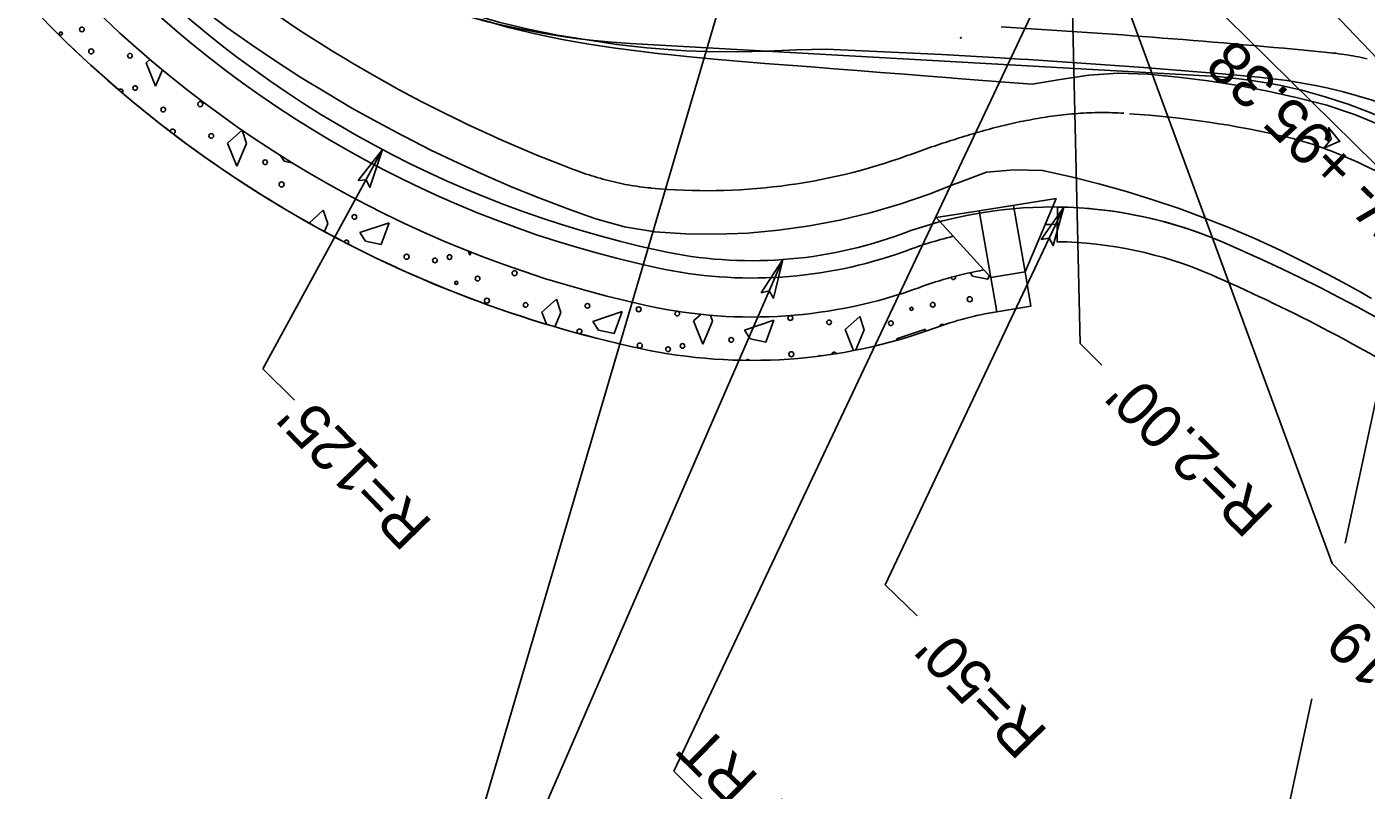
# Model space of a CAD drawing. Extents: x 1262642 to 1268358, y 767825 to 773481.
# Drawn here: x 1266640.8 to 1266795.4, y 772031 to 772119 of the extents above; entities that cross this region are included whole.
import ezdxf

# ---------------------------------------------------------------- set-up
doc = ezdxf.new("R2010")
doc.units = 0
for name, color, linetype in [('Old_Level_20', 7, 'Continuous'), ('Prop Conc 2ft 6in Curb and Gutter', 7, 'Continuous'), ('Prop Conc 4in Sidewalk', 7, 'Continuous'), ('Prop Dimension', 7, 'Continuous'), ('Prop Dimension Text', 7, 'Continuous'), ('Prop EOT', 7, 'Continuous'), ('Prop Horizontal Alignment', 7, 'Continuous'), ('Prop Lane Lines', 7, 'Continuous'), ('Prop Paved Shoulder', 7, 'Continuous'), ('Prop Shade Light', 7, 'Continuous'), ('Prop Terminator CELL', 7, 'Continuous'), ('Scratch_Level_3', 7, 'Continuous')]:
    doc.layers.add(name, color=color, linetype=linetype)

msp = doc.modelspace()

# ---------------------------------------------------------------- linework, layer by layer
at = {"layer": 'Old_Level_20'}
for p, q in [((1266750.7, 772097.82), (1266759.58, 772099.23)), ((1266759.58, 772099.23), (1266755.99, 772090.77)), ((1266745.74, 772097.04), (1266750.7, 772097.82)), ((1266750.7, 772097.81), (1266752.04, 772090.12)), ((1266755.99, 772090.77), (1266754.65, 772098.45)), ((1266752.04, 772090.12), (1266745.74, 772097.04)), ((1266752.04, 772090.12), (1266755.99, 772090.77)), ((1266752.72, 772086.18), (1266752.04, 772090.12)), ((1266755.99, 772090.77), (1266756.67, 772086.82)), ((1266756.67, 772086.82), (1266752.72, 772086.18))]:
    msp.add_line(p, q, dxfattribs=at)
at = {"layer": 'Prop Conc 2ft 6in Curb and Gutter'}
for p, q in [((1266654.56, 772114.87), (1266655.01, 772115.27)), ((1266655.64, 772112.19), (1266654.56, 772114.87)), ((1266656.45, 772114.08), (1266655.64, 772112.19)), ((1266663.94, 772105.63), (1266665.63, 772107.12)), ((1266665.63, 772107.12), (1266666.15, 772105.59)), ((1266665.02, 772102.95), (1266663.94, 772105.63)), ((1266666.15, 772105.59), (1266665.02, 772102.95)), ((1266670.07, 772104.21), (1266670.5, 772103.56)), ((1266670.5, 772103.56), (1266671.38, 772103.37)), ((1266673.36, 772096.41), (1266675.01, 772097.88)), ((1266675.01, 772097.88), (1266675.54, 772096.34)), ((1266675.54, 772096.34), (1266675.15, 772095.45)), ((1266682.61, 772096.43), (1266679.24, 772095.3)), ((1266681.69, 772093.93), (1266682.61, 772096.43)), ((1266679.24, 772095.3), (1266679.88, 772094.31)), ((1266679.88, 772094.31), (1266681.69, 772093.93)), ((1266691.91, 772092.7), (1266691.71, 772093.21)), ((1266692.07, 772093.06), (1266691.91, 772092.7)), ((1266749.66, 772090.69), (1266749.91, 772090.3)), ((1266749.91, 772090.3), (1266751.71, 772089.93)), ((1266751.71, 772089.93), (1266751.86, 772090.32)), ((1266700.22, 772086.13), (1266701.9, 772087.63)), ((1266701.9, 772087.63), (1266702.43, 772086.1)), ((1266700.78, 772084.74), (1266700.22, 772086.13)), ((1266702.43, 772086.1), (1266701.72, 772084.45)), ((1266709.5, 772086.19), (1266706.13, 772085.05)), ((1266706.13, 772085.05), (1266706.77, 772084.06)), ((1266708.58, 772083.69), (1266709.5, 772086.19)), ((1266717.72, 772085.13), (1266718.6, 772085.92)), ((1266718.8, 772082.45), (1266717.72, 772085.13)), ((1266719.93, 772085.1), (1266718.8, 772082.45)), ((1266719.69, 772085.8), (1266719.93, 772085.1)), ((1266727, 772085.19), (1266723.63, 772084.05)), ((1266726.08, 772082.69), (1266727, 772085.19)), ((1266735.23, 772084.13), (1266736.92, 772085.63)), ((1266736.92, 772085.63), (1266737.44, 772084.1)), ((1266706.77, 772084.06), (1266708.58, 772083.69)), ((1266723.63, 772084.05), (1266724.28, 772083.06)), ((1266736.2, 772081.73), (1266735.23, 772084.13)), ((1266737.44, 772084.1), (1266736.45, 772081.77)), ((1266744.51, 772084.18), (1266741.14, 772083.05)), ((1266744.41, 772083.93), (1266744.51, 772084.18)), ((1266724.28, 772083.06), (1266726.08, 772082.69)), ((1266741.14, 772083.05), (1266741.23, 772082.91))]:
    msp.add_line(p, q, dxfattribs=at)
for centre, radius in [((1266647.15, 772118.73), 0.268), ((1266644.72, 772118.26), 0.18), ((1266648.23, 772116.2), 0.285), ((1266652.7, 772115.7), 0.268), ((1266653.3, 772111.98), 0.268), ((1266656.54, 772109.49), 0.268), ((1266660.81, 772110.12), 0.292), ((1266662.08, 772106.46), 0.268), ((1266668.3, 772103.42), 0.268), ((1266670.2, 772100.87), 0.292), ((1266678.6, 772097.11), 0.268), ((1266684.62, 772092.52), 0.289), ((1266689.57, 772092.49), 0.268), ((1266687.89, 772092.1), 0.268), ((1266690.37, 772089.52), 0.18), ((1266692.81, 772090), 0.268), ((1266697.09, 772090.63), 0.292), ((1266749.61, 772087.62), 0.292), ((1266693.89, 772087.46), 0.285), ((1266698.35, 772086.96), 0.268), ((1266705.49, 772086.86), 0.268), ((1266711.4, 772086.46), 0.285), ((1266742.89, 772086.52), 0.18), ((1266745.33, 772086.99), 0.268), ((1266715.86, 772085.96), 0.268), ((1266728.9, 772085.46), 0.285), ((1266733.37, 772084.96), 0.268), ((1266740.51, 772084.86), 0.268), ((1266711.52, 772082.28), 0.289), ((1266714.79, 772081.85), 0.268), ((1266716.46, 772082.24), 0.268), ((1266722.08, 772082.93), 0.268), ((1266729.02, 772081.28), 0.289)]:
    msp.add_circle(centre, radius, dxfattribs=at)
for centre, radius, start, end in [((1266740.24, 772215.4), 127, 223.2333, 257.87), ((1266740.24, 772215.4), 131.5, 223.2333, 257.87), ((1266740.24, 772215.4), 136.5, 223.2592, 257.87), ((1266651.62, 772111.59), 0.268, 318.3312, 138.9797), ((1266657.62, 772106.95), 0.285, 170.4753, 172.1798), ((1266657.62, 772106.95), 0.285, 293.7842, 170.4753), ((1266671.46, 772097.21), 0.268, 52.9324, 66.0296), ((1266759.1, 772048.26), 48, 89.4703, 90.9427), ((1266677.68, 772094.17), 0.268, 47.9203, 169.4069), ((1266677.68, 772094.17), 0.268, 315.4588, 47.9203), ((1266759.1, 772048.26), 48, 103.7447, 110.943), ((1266724.48, 772142.07), 52, 257.87, 289.6213), ((1266747.71, 772090.17), 0.268, 185.1215, 35.1369), ((1266724.48, 772142.07), 56.5, 257.87, 290.0389), ((1266723, 772085.86), 0.268, 238.6336, 297.1958), ((1266758.89, 772048.15), 38.53, 99.2167, 110.256), ((1266704.57, 772083.93), 0.268, 14.8235, 233.9093), ((1266704.57, 772083.93), 0.268, 275.3587, 14.8235), ((1266724.48, 772142.07), 61.5, 257.87, 290.0389), ((1266746.41, 772084.45), 0.285, 45.4739, 172.2714), ((1266723.98, 772080.38), 0.292, 44.3986, 131.4308), ((1266732.29, 772080.85), 0.268, 69.0863, 122.8499), ((1266733.97, 772081.24), 0.268, 30.3392, 169.6491)]:
    msp.add_arc(centre, radius, start, end, dxfattribs=at)
at = {"layer": 'Prop Conc 4in Sidewalk'}
for centre, radius, start, end in [((1266740.24, 772215.4), 131.5, 223.2333, 257.87), ((1266740.24, 772215.4), 136.5, 223.2333, 257.87), ((1266758.89, 772048.15), 43.53, 100.1322, 110.256), ((1266724.48, 772142.07), 56.5, 257.87, 290.0389), ((1266758.89, 772048.15), 38.53, 99.2167, 110.256), ((1266724.48, 772142.07), 61.5, 257.87, 290.0389)]:
    msp.add_arc(centre, radius, start, end, dxfattribs=at)
at = {"layer": 'Prop Dimension'}
for p, q in [((1266722.9, 772128.88), (1266688.04, 772010.59)), ((1266761.3, 772127.13), (1266762.34, 772082.5)), ((1266759.33, 772125.95), (1266715.46, 772033.19)), ((1266681.85, 772104.87), (1266668.05, 772079.59)), ((1266760.45, 772098.24), (1266739.86, 772054.7)), ((1266728.03, 772092.2), (1266697.28, 772021.6))]:
    msp.add_line(p, q, dxfattribs=at)
at = {"layer": 'Prop Dimension Text'}
for p, q in [((1266820.02, 772079.89), (1266772.47, 772126.74)), ((1266791.44, 772057.15), (1266767.03, 772123.52)), ((1266762.33, 772082.5), (1266764.86, 772080.01)), ((1266668.05, 772079.59), (1266671.7, 772075.98)), ((1266832.76, 772014.09), (1266791.44, 772057.15)), ((1266739.86, 772054.7), (1266743.52, 772051.1)), ((1266715.46, 772033.19), (1266758.9, 771990.39))]:
    msp.add_line(p, q, dxfattribs=at)
for points in [[(1266792.94, 772059.49), (1266798.9, 772087.24)], [(1266785.55, 772025.08), (1266789.08, 772041.54)]]:
    msp.add_lwpolyline(points, dxfattribs=at)
at = {"layer": 'Prop EOT'}
for centre, radius, start, end in [((1266740.24, 772215.4), 125, 223.2333, 257.87), ((1266759.1, 772048.26), 50, 66.6575, 110.256), ((1266724.48, 772142.07), 50, 257.87, 290.256), ((1266699.67, 771910.54), 200, 44.1752, 66.6575)]:
    msp.add_arc(centre, radius, start, end, dxfattribs=at)
at = {"layer": 'Prop Horizontal Alignment'}
msp.add_arc((1275047.31, 780021.23), 11400, 222.993587, 225.404319, dxfattribs=at)
at = {"layer": 'Prop Lane Lines'}
msp.add_line((1266710.41, 772117.12), (1266776.78, 772113.4), dxfattribs=at)
for centre, radius, start, end in [((1275047.31, 780021.23), 11427, 222.993587, 225.36373), ((1266715.28, 772203.99), 87, 223.2333, 266.7861), ((1266773.42, 772053.49), 60, 43.9174, 86.7861)]:
    msp.add_arc(centre, radius, start, end, dxfattribs=at)
at = {"layer": 'Prop Paved Shoulder'}
for centre, radius, start, end in [((1266759.1, 772048.26), 46, 66.6575, 89.2851), ((1266699.67, 771910.54), 196, 58.2697, 66.6575)]:
    msp.add_arc(centre, radius, start, end, dxfattribs=at)
at = {"layer": 'Prop Shade Light'}
msp.add_line((1266759.73, 772098.25), (1266759.68, 772094.26), dxfattribs=at)
for centre, radius, start, end in [((1266759.1, 772048.26), 50, 66.6575, 89.2851), ((1266759.1, 772048.26), 46, 66.6575, 89.2851), ((1266699.67, 771910.54), 200, 44.1752, 66.6575), ((1266699.67, 771910.54), 196, 58.2697, 66.6575)]:
    msp.add_arc(centre, radius, start, end, dxfattribs=at)
at = {"layer": 'Prop Terminator CELL'}
for points in [[(1266679.02, 772101.3), (1266681.85, 772104.87), (1266680.39, 772100.52), (1266679.96, 772101.41)], [(1266757.83, 772094.5), (1266760.45, 772098.24), (1266759.24, 772093.81), (1266758.76, 772094.67)], [(1266725.52, 772088.38), (1266728.03, 772092.2), (1266726.95, 772087.73), (1266726.45, 772088.58)]]:
    msp.add_lwpolyline(points, close=True, dxfattribs=at)
at = {"layer": 'Scratch_Level_3'}
for points in [[(1266658.38, 772123.48), (1266658.62, 772123.25), (1266661.14, 772121.02), (1266663.87, 772118.96), (1266666.69, 772116.98), (1266669.54, 772115.07), (1266672.43, 772113.21), (1266675.36, 772111.41), (1266678.32, 772109.67), (1266681.33, 772108), (1266684.06, 772106.54)], [(1266689.63, 772121.29), (1266691.94, 772120.54), (1266695.27, 772119.59), (1266698.64, 772118.77), (1266702.04, 772118.08), (1266705.47, 772117.52), (1266708.9, 772117.01), (1266712.35, 772116.62), (1266715.8, 772116.34), (1266716.84, 772116.28)], [(1266693.03, 772119.93), (1266693.34, 772119.83), (1266696.39, 772118.97), (1266699.47, 772118.22), (1266702.57, 772117.58), (1266705.66, 772117.03), (1266708.72, 772116.57), (1266711.76, 772116.18), (1266713.57, 772115.97)], [(1266713.57, 772115.97), (1266714.76, 772115.84), (1266717.7, 772115.54), (1266720.53, 772115.28), (1266723.27, 772115.04), (1266725.97, 772114.82), (1266728.66, 772114.62), (1266731.32, 772114.42), (1266733.97, 772114.21), (1266736.63, 772113.99), (1266739.32, 772113.77), (1266742.06, 772113.56), (1266744.85, 772113.34), (1266747.4, 772113.14)], [(1266716.84, 772116.28), (1266719.27, 772116.18), (1266722.74, 772116.14), (1266726.21, 772116.21), (1266729.67, 772116.39), (1266733.06, 772116.45), (1266736.4, 772116.31), (1266739.73, 772116.15), (1266743.07, 772115.99), (1266746.4, 772115.83), (1266749.73, 772115.65), (1266753.06, 772115.46), (1266755.39, 772115.32)], [(1266790.52, 772116.12), (1266790.85, 772116.09), (1266791.18, 772116.05), (1266791.51, 772116.01), (1266791.84, 772115.98), (1266792.17, 772115.93), (1266792.5, 772115.89), (1266792.83, 772115.84), (1266793.16, 772115.79), (1266793.49, 772115.73), (1266793.82, 772115.68), (1266794.15, 772115.62), (1266794.48, 772115.56), (1266794.8, 772115.49), (1266795.13, 772115.42), (1266795.45, 772115.35)], [(1266755.39, 772115.32), (1266756.39, 772115.26), (1266759.71, 772115.05), (1266763.03, 772114.82), (1266766.35, 772114.59), (1266769.67, 772114.34), (1266772.99, 772114.09), (1266776.3, 772113.82), (1266778.29, 772113.65)], [(1266747.4, 772113.14), (1266747.69, 772113.11), (1266750.63, 772112.88), (1266753.66, 772112.64), (1266756.79, 772112.42), (1266760.04, 772112.98), (1266763.35, 772113.46), (1266766.74, 772113.68), (1266770.18, 772113.58), (1266773.65, 772113.24), (1266777.12, 772112.81), (1266780.57, 772112.26), (1266784.01, 772111.61), (1266787.42, 772110.85), (1266790.8, 772110), (1266794.13, 772108.9), (1266796.42, 772107.93)], [(1266778.29, 772113.65), (1266779.62, 772113.54), (1266782.93, 772113.23), (1266786.23, 772112.83), (1266789.51, 772112.27), (1266790.81, 772112)], [(1266790.81, 772112), (1266792.75, 772111.53), (1266795.91, 772110.61), (1266798.94, 772109.55), (1266801.82, 772108.36), (1266804.62, 772107), (1266807.32, 772105.47), (1266809.92, 772103.77), (1266812.42, 772101.91), (1266814.78, 772099.98), (1266817.07, 772098), (1266819.34, 772096), (1266821.6, 772093.98), (1266823.91, 772091.88), (1266826.27, 772089.7), (1266828.67, 772087.44), (1266829.14, 772086.98)], [(1266742.39, 772104.18), (1266742.7, 772104.29), (1266743.01, 772104.4), (1266743.33, 772104.52), (1266743.64, 772104.63), (1266743.96, 772104.74), (1266744.27, 772104.85), (1266744.58, 772104.96), (1266744.9, 772105.07), (1266745.21, 772105.18), (1266745.53, 772105.29), (1266745.85, 772105.39), (1266746.16, 772105.5), (1266746.48, 772105.61), (1266746.79, 772105.71), (1266747.11, 772105.82), (1266747.43, 772105.92), (1266747.75, 772106.02), (1266748.06, 772106.12), (1266748.38, 772106.22), (1266748.7, 772106.32), (1266749.02, 772106.42), (1266749.34, 772106.52), (1266749.66, 772106.61), (1266749.98, 772106.71), (1266750.3, 772106.8), (1266750.62, 772106.89), (1266750.94, 772106.98), (1266751.26, 772107.07), (1266751.58, 772107.16), (1266751.9, 772107.25), (1266752.22, 772107.33), (1266752.55, 772107.42), (1266752.87, 772107.5), (1266753.19, 772107.58), (1266753.52, 772107.66), (1266753.84, 772107.74), (1266754.16, 772107.81), (1266754.49, 772107.89), (1266754.82, 772107.96), (1266755.14, 772108.03), (1266755.47, 772108.1), (1266755.79, 772108.17), (1266756.12, 772108.23), (1266756.45, 772108.29), (1266756.78, 772108.35), (1266757.1, 772108.41), (1266757.43, 772108.47), (1266757.76, 772108.53), (1266758.09, 772108.58), (1266758.42, 772108.63), (1266758.75, 772108.68), (1266759.08, 772108.73), (1266759.41, 772108.77), (1266759.74, 772108.81), (1266760.07, 772108.85), (1266760.4, 772108.89), (1266760.73, 772108.93), (1266761.06, 772108.96), (1266761.4, 772108.99), (1266761.73, 772109.02), (1266762.06, 772109.04), (1266762.39, 772109.06), (1266762.73, 772109.08), (1266763.06, 772109.1), (1266763.39, 772109.12), (1266763.73, 772109.13), (1266764.06, 772109.14), (1266764.39, 772109.14), (1266764.73, 772109.15), (1266765.06, 772109.15), (1266765.39, 772109.14), (1266765.73, 772109.14), (1266766.06, 772109.13), (1266766.39, 772109.12), (1266766.72, 772109.11), (1266767.06, 772109.09), (1266767.39, 772109.07)], [(1266684.06, 772106.54), (1266684.36, 772106.38), (1266687.43, 772104.83), (1266690.53, 772103.34), (1266693.66, 772101.92), (1266696.81, 772100.56), (1266700, 772099.27), (1266703.21, 772098.04), (1266705.15, 772097.34)], [(1266786.27, 772106.3), (1266786.59, 772106.22), (1266786.91, 772106.14), (1266787.24, 772106.06), (1266787.56, 772105.97), (1266787.88, 772105.88), (1266788.2, 772105.79), (1266788.52, 772105.7), (1266788.84, 772105.6), (1266789.15, 772105.49), (1266789.47, 772105.39), (1266789.79, 772105.28), (1266790.1, 772105.17), (1266790.41, 772105.05), (1266790.72, 772104.93)], [(1266703.78, 772102.62), (1266704.1, 772102.5), (1266704.41, 772102.39), (1266704.72, 772102.28), (1266705.04, 772102.17), (1266705.35, 772102.06), (1266705.67, 772101.96), (1266705.99, 772101.85), (1266706.31, 772101.76), (1266706.62, 772101.66), (1266706.94, 772101.57), (1266707.27, 772101.48), (1266707.59, 772101.39), (1266707.91, 772101.31), (1266708.23, 772101.23), (1266708.56, 772101.15), (1266708.88, 772101.07), (1266709.21, 772101), (1266709.53, 772100.94), (1266709.86, 772100.87), (1266710.19, 772100.81), (1266710.52, 772100.75), (1266710.85, 772100.7), (1266711.18, 772100.65), (1266711.51, 772100.6), (1266711.84, 772100.56), (1266712.17, 772100.52), (1266712.5, 772100.48), (1266712.83, 772100.45)], [(1266747.92, 772100.93), (1266748.25, 772101.06), (1266751.54, 772102.26), (1266754.73, 772102.56), (1266758.02, 772102.45), (1266761.3, 772101.73), (1266764.52, 772100.92), (1266767.68, 772100.04), (1266770.75, 772099.1), (1266773.76, 772098.08), (1266776.74, 772096.98), (1266779.68, 772095.81), (1266782.57, 772094.57), (1266785.41, 772093.27), (1266788.19, 772091.91), (1266790.88, 772090.53), (1266792.69, 772089.55)], [(1266705.15, 772097.34), (1266706.44, 772096.89), (1266709.78, 772095.97), (1266713.25, 772095.39), (1266716.82, 772095.15), (1266720.4, 772095.12), (1266723.98, 772095.26), (1266727.55, 772095.58), (1266731.1, 772096.07), (1266734.62, 772096.73), (1266738.1, 772097.57), (1266741.54, 772098.58), (1266744.93, 772099.75), (1266747.92, 772100.93)], [(1266792.69, 772089.55), (1266793.45, 772089.13), (1266794.72, 772088.42), (1266795.98, 772087.7)]]:
    msp.add_lwpolyline(points, dxfattribs=at)
msp.add_lwpolyline([(1266792.27, 772105.86), (1266791.01, 772107.41), (1266791.3, 772106.09), (1266790.45, 772105.04)], close=True, dxfattribs=at)
for centre in [(1266748.58, 772117.77), (1266748.58, 772117.77), (1266792.27, 772105.86), (1266792.27, 772105.86)]:
    msp.add_circle(centre, 0.0417, dxfattribs=at)
for centre, radius, start, end in [((1266761.14, 772254.43), 162.28, 232.6506, 249.3021), ((1266696.11, 771143.9), 976.79, 84.45376, 86.64753), ((1266761.08, 772000.1), 109.14, 76.6608, 86.3381), ((1266763.85, 772035.64), 74.33, 49.2925, 68.8021), ((1266719.29, 772168.24), 68.1, 264.5601, 289.8296)]:
    msp.add_arc(centre, radius, start, end, dxfattribs=at)

# ---------------------------------------------------------------- texts
at = {"layer": 'Prop Dimension'}
for s, rotation, p in [("R=2.00'", 135.4239, (1266784.92, 772063.4)), ("R=125'", 134.2575, (1266687.77, 772061.83)), ("R=50'", 134.2575, (1266758.78, 772037.76))]:
    msp.add_text(s, height=5, rotation=rotation, dxfattribs=at).set_placement(p)
at = {"layer": 'Prop Dimension Text'}
for s, p in [('-Y38SW- +95.38', (1266815.38, 772083.07)), ('-Y38SW- +97.19', (1266829.25, 772016.27)), ("14.61' RT", (1266739.6, 772018.57))]:
    msp.add_text(s, height=5, rotation=135.4239, dxfattribs=at).set_placement(p)

doc.saveas('drawing.dxf')
